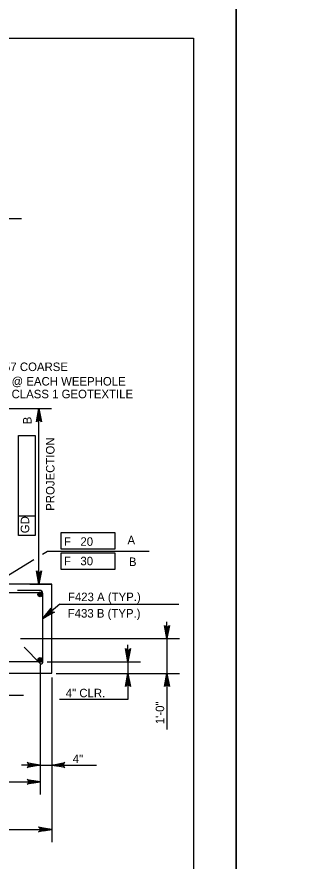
# Model space of a CAD drawing. Extents: x 638340 to 640242, y 295465 to 298435.
# Drawn here: x 639199.2 to 639303.6, y 295754.8 to 296052 of the extents above; entities that cross this region are included whole.
import ezdxf

# ---------------------------------------------------------------- set-up
doc = ezdxf.new("R2010")
doc.units = 0
for name, color, linetype in [('2', 7, 'Continuous'), ('Level 3', 7, 'Continuous'), ('Level 4', 7, 'Continuous'), ('Level 5', 7, 'Continuous'), ('Level 6', 7, 'Continuous'), ('Level 8', 7, 'Continuous'), ('Level 9', 7, 'Continuous'), ('PLT-BNDY', 7, 'Continuous')]:
    doc.layers.add(name, color=color, linetype=linetype)

msp = doc.modelspace()

# ---------------------------------------------------------------- linework, layer by layer
at = {"layer": '2'}
for p, q in [((638475.46, 296044.46), (639261.46, 296044.46)), ((639261.46, 296044.46), (639261.46, 295480.46))]:
    msp.add_line(p, q, dxfattribs=at)
at = {"layer": 'Level 3'}
for p, q in [((639166.39, 295980.95), (639200.9, 295980.95)), ((639252.06, 295836.05), (639252.06, 295838.99)), ((639200.53, 295833.1), (639256.48, 295833.1)), ((639238.32, 295827.91), (639238.32, 295830.91)), ((639252.06, 295833.1), (639252.06, 295820.83)), ((639209.87, 295824.92), (639242.81, 295824.92)), ((639238.32, 295824.92), (639238.32, 295820.83)), ((639213.05, 295820.83), (639256.48, 295820.83)), ((639213.08, 295820.83), (639242.81, 295820.83)), ((639238.32, 295817.83), (639238.32, 295811.67)), ((639252.06, 295817.88), (639252.06, 295801.11)), ((639238.32, 295811.67), (639214.19, 295811.67))]:
    msp.add_line(p, q, dxfattribs=at)
for points in [[(639252.06, 295833.1), (639251.19, 295837.75), (639251.44, 295837.39), (639251.75, 295837.21), (639252.06, 295837.16), (639252.37, 295837.21), (639252.69, 295837.39), (639252.93, 295837.75), (639252.06, 295833.1), (639252.69, 295837.39), (639252.37, 295837.21), (639252.06, 295833.1), (639252.06, 295837.16), (639251.75, 295837.21), (639252.06, 295833.1), (639251.44, 295837.39)], [(639238.32, 295824.92), (639237.44, 295829.57), (639237.69, 295829.21), (639238, 295829.03), (639238.32, 295828.97), (639238.63, 295829.03), (639238.94, 295829.21), (639239.19, 295829.57), (639238.32, 295824.92), (639238.94, 295829.21), (639238.63, 295829.03), (639238.32, 295824.92), (639238.32, 295828.97), (639238, 295829.03), (639238.32, 295824.92), (639237.69, 295829.21)], [(639238.32, 295820.83), (639239.19, 295816.18), (639238.94, 295816.53), (639238.63, 295816.72), (639238.32, 295816.77), (639238, 295816.72), (639237.69, 295816.53), (639237.44, 295816.18), (639238.32, 295820.83), (639237.69, 295816.53), (639238, 295816.72), (639238.32, 295820.83), (639238.32, 295816.77), (639238.63, 295816.72), (639238.32, 295820.83), (639238.94, 295816.53)], [(639252.06, 295820.83), (639252.93, 295816.18), (639252.69, 295816.53), (639252.37, 295816.72), (639252.06, 295816.77), (639251.75, 295816.72), (639251.44, 295816.53), (639251.19, 295816.18), (639252.06, 295820.83), (639251.44, 295816.53), (639251.75, 295816.72), (639252.06, 295820.83), (639252.06, 295816.77), (639252.37, 295816.72), (639252.06, 295820.83), (639252.69, 295816.53)]]:
    msp.add_lwpolyline(points, dxfattribs=at)
for points in [[(639251.57, 295836.05), (639252.56, 295836.05), (639252.06, 295833.1)], [(639237.82, 295827.91), (639238.81, 295827.91), (639238.32, 295824.92)], [(639237.82, 295817.83), (639238.81, 295817.83), (639238.32, 295820.83)], [(639251.57, 295817.88), (639252.56, 295817.88), (639252.06, 295820.83)]]:
    msp.add_lwpolyline(points, close=True, dxfattribs=at)
at = {"layer": 'Level 4'}
for p, q in [((639162.69, 295914.07), (639211.41, 295914.07)), ((639206.99, 295852.26), (639206.99, 295914.07)), ((639206.99, 295852.26), (639206.99, 295914.07)), ((639199.8, 295869.35), (639199.8, 295904.58)), ((639199.8, 295904.58), (639205.69, 295904.58)), ((639205.69, 295904.58), (639205.69, 295869.35)), ((639205.69, 295876.18), (639199.8, 295876.18)), ((639214.82, 295870.42), (639233.73, 295870.42)), ((639214.82, 295864.52), (639214.82, 295870.42)), ((639233.73, 295870.42), (639233.73, 295864.52)), ((639205.69, 295869.35), (639199.8, 295869.35)), ((639208.23, 295862.8), (639210.02, 295863.9)), ((639210.02, 295863.9), (639245.81, 295863.9)), ((639233.73, 295864.52), (639214.82, 295864.52)), ((639186.01, 295849.19), (639205.18, 295860.93)), ((639186.01, 295849.19), (639205.18, 295860.93)), ((639214.82, 295863.31), (639233.73, 295863.31)), ((639214.82, 295857.42), (639214.82, 295863.31)), ((639233.73, 295863.31), (639233.73, 295857.42)), ((639233.73, 295857.42), (639214.82, 295857.42)), ((639203.83, 295852.26), (639211.41, 295852.26)), ((639203.83, 295852.26), (639211.41, 295852.26)), ((639203.83, 295852.26), (639211.41, 295852.26)), ((639214.38, 295845.17), (639208.31, 295840.15)), ((639214.38, 295845.17), (639256.27, 295845.17)), ((639207.46, 295823.92), (639207.46, 295778.25)), ((639211.51, 295819.38), (639211.51, 295761.48)), ((639211.51, 295799.1), (639211.51, 295787.63)), ((639207.46, 295788.59), (639200.88, 295788.59)), ((639207.46, 295788.59), (639227.29, 295788.59)), ((639101.52, 295782.67), (639207.46, 295782.67)), ((639097.46, 295765.9), (639211.51, 295765.9))]:
    msp.add_line(p, q, dxfattribs=at)
for points in [[(639206.99, 295914.07), (639207.87, 295909.42), (639207.62, 295909.78), (639207.31, 295909.96), (639206.99, 295910.01), (639206.68, 295909.96), (639206.37, 295909.78), (639206.12, 295909.42), (639206.99, 295914.07), (639206.37, 295909.78), (639206.68, 295909.96), (639206.99, 295914.07), (639206.99, 295910.01), (639207.31, 295909.96), (639206.99, 295914.07), (639207.62, 295909.78)], [(639206.99, 295852.26), (639206.12, 295856.91), (639206.37, 295856.56), (639206.68, 295856.37), (639206.99, 295856.32), (639207.31, 295856.37), (639207.62, 295856.56), (639207.87, 295856.91), (639206.99, 295852.26), (639207.62, 295856.56), (639207.31, 295856.37), (639206.99, 295852.26), (639206.99, 295856.32), (639206.68, 295856.37), (639206.99, 295852.26), (639206.37, 295856.56)], [(639206.99, 295852.26), (639206.12, 295856.91), (639206.37, 295856.56), (639206.68, 295856.37), (639206.99, 295856.32), (639207.31, 295856.37), (639207.62, 295856.56), (639207.87, 295856.91), (639206.99, 295852.26), (639207.62, 295856.56), (639207.31, 295856.37), (639206.99, 295852.26), (639206.99, 295856.32), (639206.68, 295856.37), (639206.99, 295852.26), (639206.37, 295856.56)], [(639208.31, 295840.16), (639211.34, 295843.79), (639211.22, 295843.37), (639211.28, 295843.01), (639211.44, 295842.74), (639211.67, 295842.53), (639212.02, 295842.41), (639212.45, 295842.45), (639208.31, 295840.16), (639212.02, 295842.41), (639211.67, 295842.53), (639208.31, 295840.16), (639211.44, 295842.74), (639211.28, 295843.01), (639208.31, 295840.16), (639211.22, 295843.37)], [(639207.46, 295788.59), (639202.81, 295787.72), (639203.16, 295787.96), (639203.35, 295788.28), (639203.4, 295788.59), (639203.35, 295788.9), (639203.16, 295789.21), (639202.81, 295789.46), (639207.46, 295788.59), (639203.16, 295789.21), (639203.35, 295788.9), (639207.46, 295788.59), (639203.4, 295788.59), (639203.35, 295788.28), (639207.46, 295788.59), (639203.16, 295787.96)], [(639211.51, 295788.59), (639216.17, 295789.46), (639215.81, 295789.21), (639215.62, 295788.9), (639215.57, 295788.59), (639215.62, 295788.28), (639215.81, 295787.96), (639216.17, 295787.72), (639211.51, 295788.59), (639215.81, 295787.96), (639215.62, 295788.28), (639211.51, 295788.59), (639215.57, 295788.59), (639215.62, 295788.9), (639211.51, 295788.59), (639215.81, 295789.21)], [(639207.46, 295782.67), (639202.81, 295781.79), (639203.16, 295782.04), (639203.35, 295782.35), (639203.4, 295782.67), (639203.35, 295782.98), (639203.16, 295783.29), (639202.81, 295783.54), (639207.46, 295782.67), (639203.16, 295783.29), (639203.35, 295782.98), (639207.46, 295782.67), (639203.4, 295782.67), (639203.35, 295782.35), (639207.46, 295782.67), (639203.16, 295782.04)], [(639211.51, 295765.9), (639206.86, 295765.02), (639207.22, 295765.27), (639207.41, 295765.58), (639207.46, 295765.9), (639207.41, 295766.21), (639207.22, 295766.52), (639206.86, 295766.77), (639211.51, 295765.9), (639207.22, 295766.52), (639207.41, 295766.21), (639211.51, 295765.9), (639207.46, 295765.9), (639207.41, 295765.58), (639211.51, 295765.9), (639207.22, 295765.27)]]:
    msp.add_lwpolyline(points, dxfattribs=at)
for points in [[(639206.5, 295911.12), (639207.48, 295911.12), (639206.99, 295914.07)], [(639206.5, 295855.21), (639207.48, 295855.21), (639206.99, 295852.26)], [(639206.5, 295855.21), (639207.48, 295855.21), (639206.99, 295852.26)], [(639204.38, 295788.1), (639204.38, 295789.08), (639207.32, 295788.59)], [(639214.74, 295789.08), (639214.74, 295788.1), (639211.79, 295788.59)], [(639204.51, 295783.16), (639204.51, 295782.18), (639207.46, 295782.67)], [(639208.57, 295766.39), (639208.57, 295765.41), (639211.51, 295765.9)]]:
    msp.add_lwpolyline(points, close=True, dxfattribs=at)
at = {"layer": 'Level 5'}
for p, q in [((639207.53, 295852.25), (639207.53, 295852.25)), ((639207.53, 295852.25), (639207.53, 295852.25)), ((639211.28, 295852.25), (639211.28, 295852.25)), ((639211.28, 295852.25), (639211.28, 295852.25))]:
    msp.add_line(p, q, dxfattribs=at)
at = {"layer": 'Level 6'}
for p, q in [((639208.3, 295849.19), (639100.68, 295849.19)), ((639199.45, 295850.09), (639207.29, 295850.09)), ((639208.31, 295824.71), (639208.31, 295849.06)), ((639201.74, 295830.05), (639207.43, 295824.35)), ((639100.67, 295825), (639208.31, 295825))]:
    msp.add_line(p, q, dxfattribs=at)
for centre, radius in [((639207.46, 295848.62), 0.832), ((639207.46, 295848.62), 0.624), ((639207.46, 295848.62), 0.416), ((639207.46, 295848.62), 0.208), ((639207.46, 295825.58), 0.832), ((639207.46, 295825.58), 0.624), ((639207.46, 295825.58), 0.416), ((639207.46, 295825.58), 0.208)]:
    msp.add_circle(centre, radius, dxfattribs=at)
for centre, radius, start, end in [((639207.28, 295849.06), 1.02, 0, 90), ((639207.8, 295824.71), 0.511, 225, 0)]:
    msp.add_arc(centre, radius, start, end, dxfattribs=at)
at = {"layer": 'Level 8'}
msp.add_line((639201.61, 295813.11), (639195.48, 295813.11), dxfattribs=at)
at = {"layer": 'Level 9'}
for p, q in [((639211.51, 295852.26), (639157.98, 295852.26)), ((639211.51, 295852.26), (639157.98, 295852.26)), ((639211.51, 295852.26), (639157.98, 295852.26)), ((639211.51, 295820.91), (639211.51, 295852.26)), ((639097.46, 295820.91), (639211.51, 295820.91))]:
    msp.add_line(p, q, dxfattribs=at)
at = {"layer": 'PLT-BNDY'}
for points in [[(638435.46, 296059.46), (639276.46, 296059.46), (639276.46, 295465.46), (638435.46, 295465.46)], [(639276.46, 296059.46), (640117.46, 296059.46), (640117.46, 295465.46), (639276.46, 295465.46)]]:
    msp.add_lwpolyline(points, close=True, dxfattribs=at)

# ---------------------------------------------------------------- texts
at = {"layer": 'Level 3'}
for s, height, p in [('1/2 C.Y. NO. 57 COARSE', 3.0001, (639170.84, 295927.27)), ('4" CLR.', 3, (639216.44, 295812.42)), ('4"', 3, (639218.9, 295789.28))]:
    msp.add_text(s, height=height, dxfattribs=at).set_placement(p)
msp.add_text('1\'-0"', height=3, rotation=90, dxfattribs=at).set_placement((639251.12, 295802.96))
at = {"layer": 'Level 4'}
for s, height, p in [('AGGREGATE @ EACH WEEPHOLE', 3.0001, (639170.83, 295922.18)), ('WRAPPED IN CLASS 1 GEOTEXTILE', 3.0001, (639170.83, 295917.69)), ('F   20', 3, (639215.8, 295865.75)), ('A', 3, (639238.18, 295866.27)), ('F   30', 3, (639215.8, 295858.9)), ('B', 3, (639238.68, 295858.64)), ('F423 A (TYP.)', 3.0001, (639217.21, 295846.27)), ('F433 B (TYP.)', 3.0001, (639217.13, 295840.49))]:
    msp.add_text(s, height=height, dxfattribs=at).set_placement(p)
for s, p in [('B', (639204.39, 295908.53)), ('PROJECTION', (639212.47, 295878.07)), ('GD', (639203.56, 295870.18))]:
    msp.add_text(s, height=3, rotation=90, dxfattribs=at).set_placement(p)

doc.saveas('drawing.dxf')
